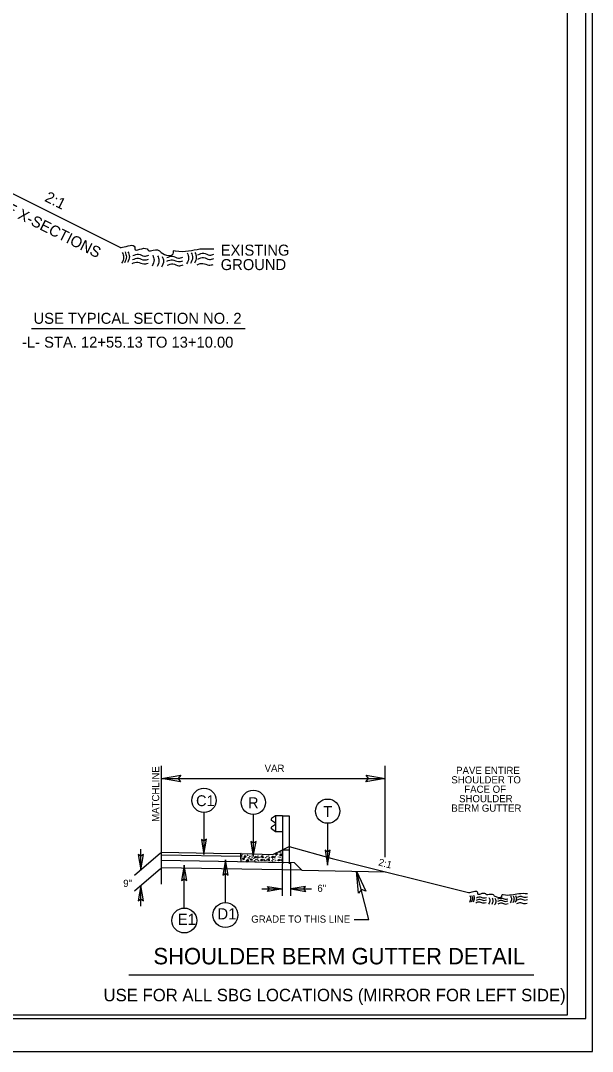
# Model space of a CAD drawing. Extents: x 575722 to 576066, y -53107 to -52774.
# Drawn here: x 575926.1 to 575965, y -52908.8 to -52838.6 of the extents above; entities that cross this region are included whole.
import ezdxf

# ---------------------------------------------------------------- set-up
doc = ezdxf.new("R2010")
doc.units = 0
for name, color, linetype in [('Old_Level_1', 7, 'Continuous'), ('Old_Level_11', 7, 'Continuous'), ('Old_Level_2', 7, 'Continuous'), ('Old_Level_20', 7, 'Continuous'), ('Old_Level_21', 7, 'Continuous'), ('Prop Dimension Text', 7, 'Continuous'), ('Prop DSN Text', 7, 'Continuous'), ('Prop Terminator CELL', 7, 'Continuous'), ('Sheet Cutting Line CELL', 7, 'Continuous'), ('Sheet Plot Border Inside CELL', 7, 'Continuous'), ('Sheet Plot Border Outside CELL', 7, 'Continuous'), ('Sheet Typical CELL', 7, 'Continuous'), ('Typical Curb CELL', 7, 'Continuous'), ('Typical Guardrail CELL', 7, 'Continuous'), ('Typical Slope Point Local CELL', 7, 'Continuous'), ('Typical Terminator CELL', 7, 'Continuous'), ('Typical Text Grade Point CELL', 7, 'Continuous'), ('Typical Text Label CELL', 7, 'Continuous')]:
    doc.layers.add(name, color=color, linetype=linetype)

msp = doc.modelspace()

# ---------------------------------------------------------------- linework, layer by layer
at = {"layer": 'Old_Level_1'}
for p, q in [((575943.878, -52895.041), (575944.342, -52894.809)), ((575944.342, -52894.809), (575947.258, -52895.62)), ((575935.647, -52895.403), (575935.647, -52895.194)), ((575935.647, -52895.194), (575939.199, -52895.253)), ((575941.062, -52895.497), (575935.647, -52895.403)), ((575941.059, -52895.284), (575941.059, -52895.862)), ((575947.258, -52895.62), (575956.55, -52897.943)), ((575944.699, -52895.925), (575935.647, -52895.769)), ((575945.203, -52896.43), (575935.647, -52896.265)), ((575944.699, -52895.925), (575945.203, -52896.43)), ((575945.203, -52896.43), (575950.879, -52896.525))]:
    msp.add_line(p, q, dxfattribs=at)
msp.add_lwpolyline([(575939.199, -52895.253), (575941.059, -52895.284), (575941.062, -52895.497)], dxfattribs=at)
at = {"layer": 'Old_Level_11'}
for p, q in [((575943.878, -52898.161), (575943.878, -52895.996)), ((575944.456, -52898.161), (575944.456, -52895.893))]:
    msp.add_line(p, q, dxfattribs=at)
for points in [[(575934.059, -52895.346), (575934.239, -52896.392), (575934.425, -52895.341), (575934.239, -52895.474)], [(575934.059, -52895.346), (575934.239, -52896.392), (575934.425, -52895.341), (575934.239, -52895.474)], [(575934.419, -52898.508), (575934.239, -52897.463), (575934.054, -52898.514), (575934.239, -52898.381)], [(575934.419, -52898.508), (575934.239, -52897.463), (575934.054, -52898.514), (575934.239, -52898.381)]]:
    msp.add_lwpolyline(points, close=True, dxfattribs=at)
at = {"layer": 'Old_Level_2'}
for points in [[(575932.845, -52854.005), (575932.987, -52853.989), (575933.827, -52853.989), (575933.827, -52854.109), (575934.667, -52854.109), (575934.787, -52854.229), (575934.907, -52854.229), (575935.507, -52854.229), (575935.627, -52854.349), (575936.467, -52854.349), (575936.467, -52854.229), (575936.587, -52854.229), (575938.267, -52854.109), (575939.224, -52854.109)], [(575932.981, -52854.342), (575933.075, -52854.665), (575932.94, -52855.082)], [(575933.169, -52854.315), (575933.263, -52854.638), (575933.129, -52855.055)], [(575933.37, -52854.302), (575933.465, -52854.625), (575933.33, -52855.041)], [(575933.686, -52854.833), (575934.076, -52854.739), (575934.479, -52854.86), (575934.775, -52854.806)], [(575933.7, -52854.564), (575934.09, -52854.47), (575934.493, -52854.591), (575934.788, -52854.537)], [(575935.051, -52854.531), (575935.145, -52854.853), (575935.01, -52855.27)], [(575935.387, -52854.571), (575935.481, -52854.893), (575935.346, -52855.31)], [(575935.696, -52854.611), (575935.79, -52854.934), (575935.655, -52855.35)], [(575936.012, -52854.699), (575936.401, -52854.605), (575936.805, -52854.726), (575937.1, -52854.672)], [(575936.012, -52854.941), (575936.401, -52854.846), (575936.805, -52854.967), (575937.1, -52854.914)], [(575937.403, -52854.383), (575937.497, -52854.705), (575937.362, -52855.122)], [(575937.671, -52854.369), (575937.765, -52854.692), (575937.631, -52855.109)], [(575937.927, -52854.342), (575938.021, -52854.665), (575937.886, -52855.082)], [(575938.122, -52854.793), (575938.512, -52854.699), (575938.915, -52854.82), (575939.21, -52854.766)], [(575938.135, -52854.497), (575938.525, -52854.403), (575938.928, -52854.524), (575939.224, -52854.47)], [(575933.646, -52855.102), (575934.036, -52855.008), (575934.439, -52855.129), (575934.735, -52855.075)], [(575936.039, -52855.223), (575936.428, -52855.129), (575936.831, -52855.25), (575937.127, -52855.196)], [(575938.082, -52855.182), (575938.471, -52855.088), (575938.874, -52855.209), (575939.17, -52855.156)], [(575956.55, -52897.943), (575956.639, -52897.933), (575957.168, -52897.933), (575957.168, -52898.008), (575957.696, -52898.008), (575957.771, -52898.084), (575957.847, -52898.084), (575958.224, -52898.084), (575958.3, -52898.159), (575958.828, -52898.159), (575958.828, -52898.084), (575958.903, -52898.084), (575959.96, -52898.008), (575960.561, -52898.008)], [(575956.635, -52898.155), (575956.694, -52898.358), (575956.61, -52898.62)], [(575956.754, -52898.138), (575956.813, -52898.341), (575956.728, -52898.603)], [(575956.88, -52898.13), (575956.939, -52898.332), (575956.855, -52898.595)], [(575957.079, -52898.464), (575957.324, -52898.404), (575957.578, -52898.48), (575957.764, -52898.447)], [(575957.087, -52898.294), (575957.333, -52898.235), (575957.586, -52898.311), (575957.772, -52898.278)], [(575957.937, -52898.273), (575957.996, -52898.476), (575957.911, -52898.738)], [(575958.148, -52898.299), (575958.207, -52898.501), (575958.123, -52898.764)], [(575958.342, -52898.324), (575958.402, -52898.527), (575958.317, -52898.789)], [(575958.541, -52898.379), (575958.786, -52898.32), (575959.04, -52898.396), (575959.226, -52898.362)], [(575958.541, -52898.531), (575958.786, -52898.472), (575959.04, -52898.548), (575959.226, -52898.514)], [(575959.416, -52898.18), (575959.475, -52898.383), (575959.39, -52898.645)], [(575959.585, -52898.172), (575959.644, -52898.375), (575959.56, -52898.637)], [(575959.745, -52898.155), (575959.805, -52898.358), (575959.72, -52898.62)], [(575959.868, -52898.438), (575960.113, -52898.379), (575960.367, -52898.455), (575960.553, -52898.421)], [(575959.877, -52898.252), (575960.122, -52898.193), (575960.375, -52898.269), (575960.561, -52898.235)], [(575957.054, -52898.633), (575957.299, -52898.573), (575957.552, -52898.649), (575957.738, -52898.616)], [(575958.558, -52898.709), (575958.803, -52898.649), (575959.057, -52898.726), (575959.243, -52898.692)], [(575959.843, -52898.683), (575960.088, -52898.624), (575960.341, -52898.7), (575960.527, -52898.666)]]:
    msp.add_spline(points, degree=3, dxfattribs=at)
at = {"layer": 'Old_Level_21'}
for p, q in [((575935.647, -52897.367), (575935.647, -52889.321)), ((575950.879, -52895.537), (575950.879, -52889.321)), ((575933.812, -52896.755), (575935.593, -52895.239)), ((575934.239, -52896.392), (575934.239, -52894.992)), ((575933.803, -52897.834), (575935.593, -52896.311)), ((575949.767, -52899.778), (575948.912, -52896.492)), ((575934.239, -52898.863), (575934.239, -52897.463)), ((575942.478, -52897.694), (575943.878, -52897.694)), ((575944.456, -52897.694), (575945.856, -52897.694)), ((575948.753, -52899.778), (575949.767, -52899.778))]:
    msp.add_line(p, q, dxfattribs=at)
at = {"layer": 'Prop Dimension Text'}
for p, q in [((575935.647, -52890.174), (575950.879, -52890.174)), ((575938.54, -52892.493), (575938.54, -52895.345)), ((575941.901, -52892.631), (575941.901, -52895.483)), ((575946.956, -52893.229), (575946.956, -52896.081)), ((575937.198, -52899), (575937.198, -52896.083)), ((575940.001, -52898.629), (575940.001, -52895.712))]:
    msp.add_line(p, q, dxfattribs=at)
for centre, radius in [((575938.54, -52891.666), 0.828), ((575941.901, -52891.804), 0.828), ((575946.956, -52892.401), 0.828), ((575937.198, -52899.847), 0.847), ((575940.001, -52899.476), 0.847)]:
    msp.add_circle(centre, radius, dxfattribs=at)
at = {"layer": 'Prop DSN Text'}
msp.add_line((575926.812, -52859.536), (575941.343, -52859.536), dxfattribs=at)
at = {"layer": 'Prop Terminator CELL'}
for points in [[(575942.874, -52897.521), (575943.878, -52897.694), (575942.869, -52897.872), (575942.997, -52897.694)], [(575945.46, -52897.521), (575944.456, -52897.694), (575945.466, -52897.872), (575945.337, -52897.694)]]:
    msp.add_lwpolyline(points, close=True, dxfattribs=at)
at = {"layer": 'Sheet Cutting Line CELL'}
msp.add_line((575796.575, -52908.762), (575964.975, -52908.762), dxfattribs=at)
at = {"layer": 'Sheet Plot Border Inside CELL'}
msp.add_lwpolyline([(575964.525, -52801.007), (575797.875, -52801.007), (575797.875, -52906.517), (575964.525, -52906.517)], close=True, dxfattribs=at)
at = {"layer": 'Sheet Plot Border Outside CELL'}
msp.add_lwpolyline([(575964.975, -52798.762), (575796.575, -52798.762), (575796.575, -52908.762), (575964.975, -52908.762)], close=True, dxfattribs=at)
at = {"layer": 'Sheet Typical CELL'}
msp.add_lwpolyline([(575963.275, -52801.262), (575813.275, -52801.262), (575813.275, -52906.262), (575963.275, -52906.262)], close=True, dxfattribs=at)
at = {"layer": 'Typical Curb CELL'}
for p, q in [((575941.059, -52895.284), (575941.059, -52895.284)), ((575941.059, -52895.673), (575941.059, -52895.294)), ((575941.069, -52895.285), (575943.236, -52895.362)), ((575941.173, -52895.611), (575941.188, -52895.695)), ((575941.316, -52895.652), (575941.173, -52895.611)), ((575941.188, -52895.695), (575941.316, -52895.652)), ((575941.28, -52895.531), (575941.361, -52895.42)), ((575941.393, -52895.526), (575941.28, -52895.531)), ((575941.361, -52895.42), (575941.393, -52895.526)), ((575941.701, -52895.735), (575941.782, -52895.623)), ((575941.782, -52895.623), (575941.814, -52895.729)), ((575941.995, -52895.579), (575942.053, -52895.472)), ((575942.149, -52895.542), (575941.995, -52895.579)), ((575942.053, -52895.472), (575942.149, -52895.542)), ((575942.415, -52895.783), (575942.474, -52895.676)), ((575942.447, -52895.531), (575942.527, -52895.42)), ((575942.559, -52895.526), (575942.447, -52895.531)), ((575942.474, -52895.676), (575942.57, -52895.746)), ((575942.527, -52895.42), (575942.559, -52895.526)), ((575942.867, -52895.735), (575942.947, -52895.623)), ((575942.947, -52895.623), (575942.979, -52895.729)), ((575943.16, -52895.579), (575943.219, -52895.472)), ((575943.315, -52895.542), (575943.16, -52895.579)), ((575943.219, -52895.472), (575943.315, -52895.542)), ((575943.236, -52895.362), (575943.878, -52895.041)), ((575943.421, -52895.372), (575943.479, -52895.265)), ((575943.576, -52895.335), (575943.421, -52895.372)), ((575943.479, -52895.265), (575943.576, -52895.335)), ((575943.581, -52895.783), (575943.639, -52895.676)), ((575943.639, -52895.676), (575943.735, -52895.746)), ((575943.7, -52895.352), (575943.715, -52895.437)), ((575943.844, -52895.394), (575943.7, -52895.352)), ((575943.715, -52895.437), (575943.844, -52895.394)), ((575943.878, -52895.911), (575943.878, -52895.041)), ((575943.878, -52895.911), (575941.059, -52895.862)), ((575941.432, -52895.809), (575941.491, -52895.703)), ((575941.587, -52895.773), (575941.432, -52895.809)), ((575941.491, -52895.703), (575941.587, -52895.773)), ((575941.814, -52895.729), (575941.701, -52895.735)), ((575942.57, -52895.746), (575942.415, -52895.783)), ((575942.979, -52895.729), (575942.867, -52895.735)), ((575943.735, -52895.746), (575943.581, -52895.783))]:
    msp.add_line(p, q, dxfattribs=at)
for centre in [(575941.143, -52895.45), (575941.178, -52895.333), (575941.29, -52895.573), (575941.521, -52895.403), (575941.563, -52895.654), (575941.576, -52895.569), (575941.598, -52895.537), (575941.629, -52895.601), (575941.659, -52895.483), (575941.73, -52895.485), (575941.777, -52895.456), (575941.82, -52895.564), (575941.941, -52895.607), (575942.002, -52895.528), (575942.193, -52895.543), (575942.197, -52895.66), (575942.209, -52895.496), (575942.219, -52895.44), (575942.272, -52895.574), (575942.362, -52895.531), (575942.449, -52895.522), (575942.561, -52895.569), (575942.639, -52895.644), (575942.742, -52895.569), (575942.794, -52895.601), (575942.825, -52895.483), (575942.942, -52895.456), (575942.986, -52895.564), (575943.167, -52895.528), (575943.194, -52895.623), (575943.359, -52895.543), (575943.363, -52895.66), (575943.375, -52895.496), (575943.428, -52895.321), (575943.455, -52895.416), (575943.615, -52895.522), (575943.681, -52895.21), (575943.727, -52895.569), (575943.733, -52895.242), (575943.764, -52895.123), (575943.817, -52895.314), (575941.087, -52895.78), (575941.199, -52895.828), (575941.439, -52895.758), (575941.466, -52895.853), (575941.997, -52895.773), (575942.049, -52895.805), (575942.08, -52895.687), (575942.15, -52895.689), (575942.241, -52895.768), (575942.422, -52895.731), (575942.614, -52895.746), (575942.63, -52895.699), (575942.692, -52895.777), (575942.782, -52895.735), (575942.869, -52895.726), (575942.981, -52895.773), (575943.162, -52895.773), (575943.215, -52895.805), (575943.246, -52895.687), (575943.407, -52895.768), (575943.588, -52895.731), (575943.614, -52895.826), (575943.78, -52895.746), (575943.796, -52895.699)]:
    msp.add_circle(centre, 0.00749, dxfattribs=at)
msp.add_arc((575941.069, -52895.294), 0.00972, 87.95199, 180, dxfattribs=at)
at = {"layer": 'Typical Guardrail CELL'}
for p, q in [((575943.414, -52892.721), (575943.143, -52892.911)), ((575943.878, -52892.721), (575943.414, -52892.721)), ((575943.414, -52892.721), (575943.414, -52893.804)), ((575943.878, -52892.721), (575943.878, -52895.041)), ((575943.878, -52892.721), (575944.342, -52892.721)), ((575944.342, -52892.721), (575944.342, -52895.041)), ((575943.414, -52893.219), (575943.143, -52893.03)), ((575943.414, -52893.306), (575943.143, -52893.496)), ((575943.414, -52893.263), (575943.414, -52893.219)), ((575943.414, -52893.263), (575943.414, -52893.306)), ((575943.414, -52893.804), (575943.143, -52893.614)), ((575943.878, -52893.804), (575943.414, -52893.804)), ((575943.878, -52895.041), (575944.342, -52895.041)), ((575943.878, -52895.041), (575943.878, -52895.982)), ((575944.342, -52895.041), (575944.342, -52895.982))]:
    msp.add_line(p, q, dxfattribs=at)
for centre, start, end in [((575943.185, -52892.97), 125.00297, 235.0112), ((575943.185, -52893.555), 125.0059, 235.0366)]:
    msp.add_arc(centre, 0.0725, start, end, dxfattribs=at)
at = {"layer": 'Typical Slope Point Local CELL'}
msp.add_line((575932.845, -52854.005), (575921.682, -52848.423), dxfattribs=at)
at = {"layer": 'Typical Terminator CELL'}
for points in [[(575936.953, -52890.399), (575935.647, -52890.174), (575936.96, -52889.942), (575936.793, -52890.174)], [(575949.572, -52889.949), (575950.879, -52890.174), (575949.565, -52890.407), (575949.732, -52890.174)], [(575938.364, -52894.323), (575938.54, -52895.345), (575938.721, -52894.317), (575938.54, -52894.448)], [(575941.725, -52894.462), (575941.901, -52895.483), (575942.083, -52894.456), (575941.901, -52894.586)], [(575946.78, -52895.059), (575946.956, -52896.081), (575947.137, -52895.053), (575946.956, -52895.184)], [(575937.378, -52897.128), (575937.198, -52896.083), (575937.013, -52897.134), (575937.198, -52897)], [(575940.181, -52896.757), (575940.001, -52895.712), (575939.815, -52896.763), (575940.001, -52896.629)], [(575949.059, -52897.976), (575948.912, -52896.492), (575949.557, -52897.848), (575949.255, -52897.736)]]:
    msp.add_lwpolyline(points, close=True, dxfattribs=at)
at = {"layer": 'Typical Text Label CELL'}
msp.add_line((575933.437, -52903.542), (575961.002, -52903.542), dxfattribs=at)

# ---------------------------------------------------------------- texts
at = {"layer": 'Old_Level_11'}
msp.add_text('6" ', height=0.49, rotation=359.99657, dxfattribs=at).set_placement((575946.259, -52897.9))
at = {"layer": 'Old_Level_20'}
for s, height, p in [('C1', 0.7408, (575938.002, -52892.059)), ('R', 0.741, (575941.54, -52892.197)), ('T', 0.741, (575946.666, -52892.795)), ('D1', 0.7579, (575939.458, -52899.772)), ('E1', 0.7579, (575936.758, -52900.143))]:
    msp.add_text(s, height=height, dxfattribs=at).set_placement(p)
at = {"layer": 'Old_Level_21'}
for s, p in [('VAR', (575942.669, -52889.724)), ('SHOULDER TO', (575955.377, -52890.509)), ('PAVE ENTIRE', (575955.702, -52889.866)), ('FACE OF', (575956.258, -52891.151)), (' SHOULDER', (575955.723, -52891.793)), ('BERM GUTTER', (575955.376, -52892.436)), ('GRADE TO THIS LINE', (575941.758, -52899.996))]:
    msp.add_text(s, height=0.49, dxfattribs=at).set_placement(p)
for s, rotation, p in [('MATCHLINE', 90, (575935.495, -52893.128)), (' 2:1', 345.60468, (575950.201, -52896.044))]:
    msp.add_text(s, height=0.49, rotation=rotation, dxfattribs=at).set_placement(p)
at = {"layer": 'Prop Dimension Text'}
msp.add_text('9"', height=0.49, dxfattribs=at).set_placement((575933.046, -52897.56))
at = {"layer": 'Prop DSN Text'}
for s, p in [('USE TYPICAL SECTION NO. 2', (575926.943, -52859.207)), ('-L- STA. 12+55.13 TO 13+10.00', (575926.158, -52860.832))]:
    msp.add_text(s, height=0.75, dxfattribs=at).set_placement(p)
at = {"layer": 'Typical Slope Point Local CELL'}
for s, p in [('SEE X-SECTIONS', (575923.763, -52850.986)), ('2:1', (575927.647, -52850.823))]:
    msp.add_text(s, height=0.75, rotation=333.43404, dxfattribs=at).set_placement(p)
at = {"layer": 'Typical Text Grade Point CELL'}
for s, p in [('EXISTING', (575939.68, -52854.564)), ('GROUND', (575939.68, -52855.548))]:
    msp.add_text(s, height=0.75, dxfattribs=at).set_placement(p)
at = {"layer": 'Typical Text Label CELL'}
for s, height, p in [('SHOULDER BERM GUTTER DETAIL', 1.12, (575935.1, -52902.835)), ('USE FOR ALL SBG LOCATIONS (MIRROR FOR LEFT SIDE)', 0.85, (575931.707, -52905.35))]:
    msp.add_text(s, height=height, dxfattribs=at).set_placement(p)

doc.saveas('drawing.dxf')
